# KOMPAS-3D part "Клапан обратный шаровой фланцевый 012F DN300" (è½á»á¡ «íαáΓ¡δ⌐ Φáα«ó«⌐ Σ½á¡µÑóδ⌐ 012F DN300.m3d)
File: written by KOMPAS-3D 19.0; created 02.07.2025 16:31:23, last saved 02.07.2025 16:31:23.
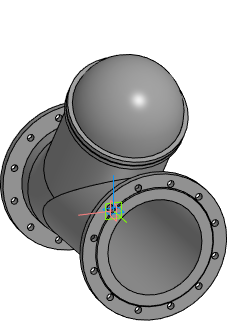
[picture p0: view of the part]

Document properties: Полное имя файла: E:\Dendor Работа Сачек\3D для проектировщиков\5.3 Тип 012F, 012F.Z Клапан обратный шаровой фланцевый\stp_Клапан обратный шаровой фланцевый 012F\Клапан обратный шаровой фланцевый 012F DN300.m3d

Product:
- Part/product: Клапан обратный шаровой фланцевый 012F DN300

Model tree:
1. Операция без истории:1  (labels: Клапан обратный шаровой фланцевый 012F DN300)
